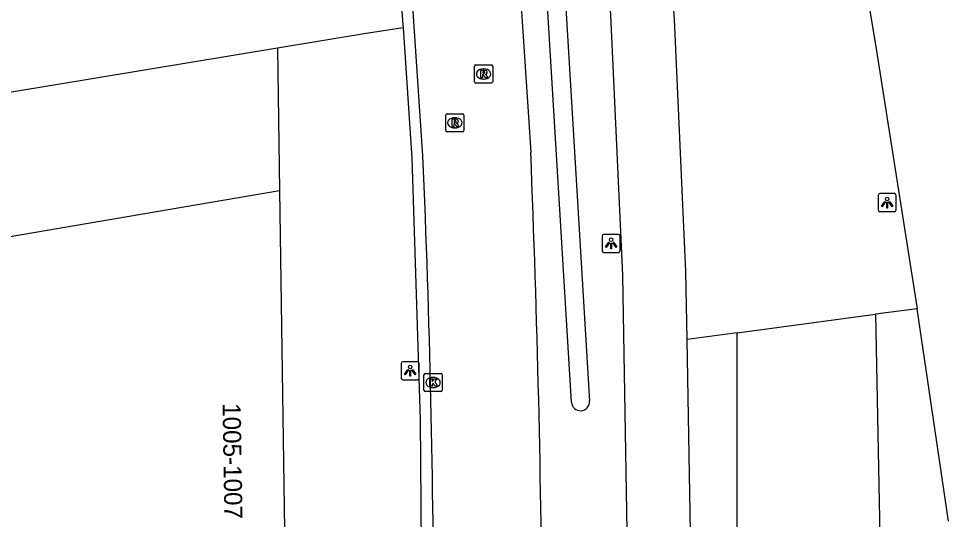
# Model space of a CAD drawing. Extents: x 154324 to 155743, y 382939 to 384183.
# Drawn here: x 155048.2 to 155099.6, y 383314 to 383341.7 of the extents above; entities that cross this region are included whole.
import ezdxf

# ---------------------------------------------------------------- set-up
doc = ezdxf.new("R2010")
doc.units = 0
for name, color, linetype in [('IMGEO_Berm_groen', 7, 'Continuous'), ('IMGEO_Fietspad_gesloten', 7, 'Continuous'), ('IMGEO_Grasland_agrarisch', 7, 'Continuous'), ('IMGEO_Greppel_droge_sloot', 7, 'Continuous'), ('IMGEO_Kolk', 7, 'Continuous'), ('IMGEO_Lichtpunt', 7, 'Continuous'), ('IMGEO_Pand', 7, 'Continuous'), ('IMGEO_Pand_nummerreeks', 7, 'Continuous'), ('IMGEO_Parkeervlak_open', 7, 'Continuous'), ('IMGEO_Rijbaan_lokaal_gesloten', 7, 'Continuous'), ('IMGEO_Rijbaan_lokaal_open', 7, 'Continuous'), ('IMGEO_Rijbaan_regionaal_gesloten', 7, 'Continuous'), ('IMGEO_Rioolput', 7, 'Continuous')]:
    doc.layers.add(name, color=color, linetype=linetype)

msp = doc.modelspace()

# ---------------------------------------------------------------- linework, layer by layer
at = {"layer": 'IMGEO_Berm_groen'}
for points in [[(155097.848, 383325.634), (155095.535, 383325.326)], [(155095.535, 383325.326), (155095.807, 383312.144), (155096.776, 383295.415), (155092.963, 383270.8), (155089.107, 383257.395), (155085.714, 383250.375), (155080.634, 383240.078), (155071.266, 383224.593), (155061.11, 383215.947), (155071.677, 383232.691), (155081.284, 383251.493), (155083.628, 383259.846), (155086.643, 383270.638), (155087.872, 383284.02), (155087.88, 383295.431), (155087.898, 383324.309)], [(155087.898, 383324.309), (155095.535, 383325.326)], [(155087.898, 383324.309), (155085.135, 383323.941)]]:
    msp.add_lwpolyline(points, dxfattribs=at)
at = {"layer": 'IMGEO_Fietspad_gesloten'}
for points in [[(155077.17, 383394.842), (155080.905, 383341.835), (155081.566, 383327.494), (155081.827, 383312.283), (155081.9, 383290.584)], [(155085.135, 383323.941), (155085.067, 383327.696), (155084.447, 383341.596), (155080.698, 383395.149)], [(155085.424, 383290.508), (155085.346, 383312.247), (155085.135, 383323.941)]]:
    msp.add_lwpolyline(points, dxfattribs=at)
at = {"layer": 'IMGEO_Grasland_agrarisch'}
msp.add_lwpolyline([(155062.526, 383340.029), (155003.646, 383330.283)], dxfattribs=at)
at = {"layer": 'IMGEO_Greppel_droge_sloot'}
for points in [[(155078.754, 383320.472), (155076.223, 383362.405)], [(155077.221, 383362.465), (155079.752, 383320.532)]]:
    msp.add_lwpolyline(points, dxfattribs=at)
msp.add_arc((155079.253, 383320.502), 0.5, 183.4452, 3.4358, dxfattribs=at)
at = {"layer": 'IMGEO_Kolk'}
for p, q in [((155070.61, 383321.133), (155070.61, 383321.985)), ((155070.685, 383322.059), (155071.537, 383322.059)), ((155071.098, 383321.839), (155071.123, 383321.839)), ((155071.611, 383321.985), (155071.611, 383321.133)), ((155071.121, 383321.279), (155071.096, 383321.279)), ((155071.537, 383321.059), (155070.685, 383321.059))]:
    msp.add_line(p, q, dxfattribs=at)
for points in [[(155070.61, 383321.133), (155070.61, 383321.985)], [(155070.685, 383322.059), (155071.537, 383322.059)], [(155071.611, 383321.985), (155071.611, 383321.133)], [(155070.931, 383321.759), (155071.054, 383321.759), (155071.054, 383321.608), (155071.184, 383321.759), (155071.348, 383321.759), (155071.202, 383321.608), (155071.355, 383321.359), (155071.203, 383321.359), (155071.118, 383321.523), (155071.054, 383321.456), (155071.054, 383321.359), (155070.931, 383321.359), (155070.931, 383321.759)], [(155071.537, 383321.059), (155070.685, 383321.059)]]:
    msp.add_lwpolyline(points, dxfattribs=at)
for centre, start, end in [((155070.687, 383321.983), 91.552, 178.448), ((155070.687, 383321.983), 91.552, 178.448), ((155071.535, 383321.983), 1.552, 88.448), ((155071.535, 383321.983), 1.552, 88.448), ((155070.687, 383321.135), 181.552, 268.448), ((155070.687, 383321.135), 181.552, 268.448), ((155071.535, 383321.135), 271.552, 358.448), ((155071.535, 383321.135), 271.552, 358.448)]:
    msp.add_arc(centre, 0.0765, start, end, dxfattribs=at)
for centre, major_axis, ratio, start_param, end_param in [((155071.097, 383321.559), (-0.387, 0.002), 0.722429, 4.712389, 7.853982), ((155071.122, 383321.559), (-0.39, 0.002), 0.717154, 1.570796, 4.712389)]:
    msp.add_ellipse(centre, major_axis=major_axis, ratio=ratio, start_param=start_param, end_param=end_param, dxfattribs=at)
at = {"layer": 'IMGEO_Lichtpunt'}
for p, q in [((155095.685, 383331.895), (155095.685, 383331.088)), ((155095.685, 383331.895), (155095.685, 383331.088)), ((155096.587, 383331.99), (155095.779, 383331.99)), ((155096.587, 383331.99), (155095.779, 383331.99)), ((155096.681, 383331.088), (155096.681, 383331.895)), ((155096.681, 383331.088), (155096.681, 383331.895)), ((155095.779, 383330.994), (155096.587, 383330.994)), ((155095.779, 383330.994), (155096.587, 383330.994)), ((155080.446, 383329.646), (155080.446, 383328.839)), ((155080.446, 383329.646), (155080.446, 383328.839)), ((155081.348, 383329.741), (155080.54, 383329.741)), ((155081.348, 383329.741), (155080.54, 383329.741)), ((155081.442, 383328.839), (155081.442, 383329.646)), ((155081.442, 383328.839), (155081.442, 383329.646)), ((155080.54, 383328.745), (155081.348, 383328.745)), ((155080.54, 383328.745), (155081.348, 383328.745)), ((155069.348, 383322.616), (155069.348, 383321.809)), ((155069.348, 383322.616), (155069.348, 383321.809)), ((155070.25, 383322.711), (155069.442, 383322.711)), ((155070.25, 383322.711), (155069.442, 383322.711)), ((155070.344, 383321.809), (155070.344, 383322.616)), ((155070.344, 383321.809), (155070.344, 383322.616)), ((155069.442, 383321.715), (155070.25, 383321.715)), ((155069.442, 383321.715), (155070.25, 383321.715))]:
    msp.add_line(p, q, dxfattribs=at)
for points in [[(155096.059, 383331.559), (155096.098, 383331.531), (155095.91, 383331.269), (155095.872, 383331.296), (155096.059, 383331.559)], [(155096.271, 383331.531), (155096.309, 383331.558), (155096.496, 383331.296), (155096.457, 383331.268), (155096.271, 383331.531)], [(155096.161, 383331.511), (155096.208, 383331.511), (155096.208, 383331.189), (155096.161, 383331.189), (155096.161, 383331.511)], [(155080.82, 383329.31), (155080.859, 383329.282), (155080.671, 383329.02), (155080.633, 383329.047), (155080.82, 383329.31)], [(155080.922, 383329.262), (155080.969, 383329.262), (155080.969, 383328.94), (155080.922, 383328.94), (155080.922, 383329.262)], [(155081.032, 383329.282), (155081.07, 383329.309), (155081.257, 383329.047), (155081.218, 383329.019), (155081.032, 383329.282)], [(155069.722, 383322.28), (155069.761, 383322.252), (155069.573, 383321.99), (155069.535, 383322.017), (155069.722, 383322.28)], [(155069.824, 383322.232), (155069.871, 383322.232), (155069.871, 383321.91), (155069.824, 383321.91), (155069.824, 383322.232)], [(155069.934, 383322.252), (155069.972, 383322.279), (155070.159, 383322.017), (155070.12, 383321.989), (155069.934, 383322.252)]]:
    msp.add_lwpolyline(points, dxfattribs=at)
for centre in [(155096.184, 383331.693), (155080.945, 383329.444), (155069.847, 383322.414)]:
    msp.add_circle(centre, 0.0994, dxfattribs=at)
for centre, start, end in [((155095.779, 383331.895), 90, 180), ((155095.779, 383331.895), 90, 180), ((155096.587, 383331.895), 0, 90), ((155096.587, 383331.895), 0, 90), ((155095.779, 383331.088), 180, 270), ((155095.779, 383331.088), 180, 270), ((155096.587, 383331.088), 270, 0), ((155096.587, 383331.088), 270, 360), ((155080.54, 383329.646), 90, 180), ((155080.54, 383329.646), 90, 180), ((155081.348, 383329.646), 0, 90), ((155081.348, 383329.646), 0, 90), ((155080.54, 383328.839), 180, 270), ((155080.54, 383328.839), 180, 270), ((155081.348, 383328.839), 270, 0), ((155081.348, 383328.839), 270, 360), ((155069.442, 383322.616), 90, 180), ((155069.442, 383322.616), 90, 180), ((155070.25, 383322.616), 0, 90), ((155070.25, 383322.616), 0, 90), ((155069.442, 383321.809), 180, 270), ((155069.442, 383321.809), 180, 270), ((155070.25, 383321.809), 270, 0), ((155070.25, 383321.809), 270, 360)]:
    msp.add_arc(centre, 0.0946, start, end, dxfattribs=at)
at = {"layer": 'IMGEO_Pand'}
for points in [[(155023.637, 383278.886), (155015.928, 383324.201), (155062.639, 383332.154)], [(155062.639, 383332.154), (155063.103, 383299.681), (155049.179, 383297.317), (155050.459, 383289.779), (155050.501, 383289.532), (155051.339, 383284.597), (155051.381, 383284.351), (155051.414, 383284.155), (155063.294, 383286.173)]]:
    msp.add_lwpolyline(points, dxfattribs=at)
at = {"layer": 'IMGEO_Parkeervlak_open'}
for points in [[(155069.458, 383341.15), (155067.422, 383340.839), (155062.526, 383340.029)], [(155062.526, 383340.029), (155062.639, 383332.154)]]:
    msp.add_lwpolyline(points, dxfattribs=at)
at = {"layer": 'IMGEO_Rijbaan_lokaal_gesloten'}
for points in [[(155072.788, 383390.399), (155076.503, 383334.279)], [(155070.546, 383334.082), (155066.805, 383389.917)]]:
    msp.add_lwpolyline(points, dxfattribs=at)
for centre, radius, start, end in [((154286.606, 383301.933), 790.559, 0.364725, 2.34496), ((154441.799, 383306.417), 629.355, 0.059169, 2.519395)]:
    msp.add_arc(centre, radius, start, end, dxfattribs=at)
at = {"layer": 'IMGEO_Rijbaan_lokaal_open'}
for points in [[(155065.709, 383396.485), (155066.213, 383389.857), (155069.432, 383341.538), (155069.458, 383341.15)], [(155069.458, 383341.15), (155069.938, 383333.947), (155070.4, 383319.494), (155070.638, 383289.04)]]:
    msp.add_lwpolyline(points, dxfattribs=at)
at = {"layer": 'IMGEO_Rijbaan_regionaal_gesloten'}
for points in [[(155071.187, 383485.369), (155076.819, 383452.367), (155095.519, 383340.332), (155097.848, 383325.634)], [(155099.567, 383313.904), (155097.848, 383325.634)]]:
    msp.add_lwpolyline(points, dxfattribs=at)
at = {"layer": 'IMGEO_Rioolput'}
for p, q in [((155073.402, 383338.17), (155073.402, 383339.022)), ((155073.477, 383339.096), (155074.329, 383339.096)), ((155073.89, 383338.876), (155073.915, 383338.876)), ((155074.403, 383339.022), (155074.403, 383338.17)), ((155073.913, 383338.316), (155073.888, 383338.316)), ((155074.329, 383338.096), (155073.477, 383338.096)), ((155071.813, 383335.474), (155071.813, 383336.326)), ((155071.888, 383336.4), (155072.74, 383336.4)), ((155072.301, 383336.18), (155072.326, 383336.18)), ((155072.814, 383336.326), (155072.814, 383335.474)), ((155072.74, 383335.4), (155071.888, 383335.4)), ((155072.324, 383335.62), (155072.299, 383335.62))]:
    msp.add_line(p, q, dxfattribs=at)
for points in [[(155073.402, 383338.17), (155073.402, 383339.022)], [(155073.477, 383339.096), (155074.329, 383339.096)], [(155073.991, 383338.794), (155073.739, 383338.796), (155073.739, 383338.396)], [(155073.917, 383338.715), (155073.863, 383338.715), (155073.863, 383338.634)], [(155074.403, 383339.022), (155074.403, 383338.17)], [(155073.739, 383338.396), (155073.863, 383338.396), (155073.863, 383338.558), (155073.874, 383338.558)], [(155073.863, 383338.634), (155073.915, 383338.634)], [(155073.921, 383338.529), (155073.992, 383338.396), (155074.132, 383338.396), (155074.067, 383338.522)], [(155074.329, 383338.096), (155073.477, 383338.096)], [(155071.813, 383335.474), (155071.813, 383336.326)], [(155071.888, 383336.4), (155072.74, 383336.4)], [(155072.814, 383336.326), (155072.814, 383335.474)], [(155072.402, 383336.098), (155072.15, 383336.1), (155072.15, 383335.7)], [(155072.15, 383335.7), (155072.274, 383335.7), (155072.274, 383335.862), (155072.285, 383335.862)], [(155072.328, 383336.019), (155072.274, 383336.019), (155072.274, 383335.938)], [(155072.274, 383335.938), (155072.326, 383335.938)], [(155072.332, 383335.833), (155072.403, 383335.7), (155072.543, 383335.7), (155072.478, 383335.826)], [(155072.74, 383335.4), (155071.888, 383335.4)]]:
    msp.add_lwpolyline(points, dxfattribs=at)
for centre, radius, start, end in [((155073.479, 383339.02), 0.0765, 91.552, 178.448), ((155073.479, 383339.02), 0.0765, 91.552, 178.448), ((155073.923, 383338.619), 0.0964, 77.0061, 93.1865), ((155073.99, 383338.684), 0.109, 350.3612, 89.416), ((155074.327, 383339.02), 0.0765, 1.552, 88.448), ((155074.327, 383339.02), 0.0765, 1.552, 88.448), ((155073.873, 383338.505), 0.0533, 26.0293, 88.6989), ((155073.899, 383338.823), 0.19, 274.7715, 282.9687), ((155073.937, 383338.676), 0.0378, 276.6634, 79.6772), ((155073.988, 383338.684), 0.112, 277.5842, 350.9817), ((155073.972, 383338.469), 0.108, 29.5134, 73.7905), ((155073.479, 383338.172), 0.0765, 181.552, 268.448), ((155073.479, 383338.172), 0.0765, 181.552, 268.448), ((155074.327, 383338.172), 0.0765, 271.552, 358.448), ((155074.327, 383338.172), 0.0765, 271.552, 358.448), ((155071.89, 383336.324), 0.0765, 91.552, 178.448), ((155071.89, 383336.324), 0.0765, 91.552, 178.448), ((155072.738, 383336.324), 0.0765, 1.552, 88.448), ((155072.738, 383336.324), 0.0765, 1.552, 88.448), ((155072.284, 383335.809), 0.0533, 26.0293, 88.6989), ((155072.31, 383336.127), 0.19, 274.7715, 282.9687), ((155072.334, 383335.923), 0.0964, 77.0061, 93.1865), ((155072.348, 383335.98), 0.0378, 276.6634, 79.6772), ((155072.401, 383335.988), 0.109, 350.3612, 89.416), ((155072.399, 383335.988), 0.112, 277.5842, 350.9817), ((155072.383, 383335.773), 0.108, 29.5134, 73.7905), ((155071.89, 383335.476), 0.0765, 181.552, 268.448), ((155071.89, 383335.476), 0.0765, 181.552, 268.448), ((155072.738, 383335.476), 0.0765, 271.552, 358.448), ((155072.738, 383335.476), 0.0765, 271.552, 358.448)]:
    msp.add_arc(centre, radius, start, end, dxfattribs=at)
for centre, major_axis, ratio, start_param, end_param in [((155073.889, 383338.596), (-0.387, 0.002), 0.722429, 4.712389, 7.853982), ((155073.914, 383338.596), (-0.39, 0.002), 0.717154, 1.570796, 4.712389), ((155072.3, 383335.9), (-0.387, 0.002), 0.722429, 4.712389, 7.853982), ((155072.325, 383335.9), (-0.39, 0.002), 0.717154, 1.570796, 4.712389)]:
    msp.add_ellipse(centre, major_axis=major_axis, ratio=ratio, start_param=start_param, end_param=end_param, dxfattribs=at)

# ---------------------------------------------------------------- texts
at = {"layer": 'IMGEO_Pand_nummerreeks'}
msp.add_text('1005-1007', height=1, rotation=270.9378, dxfattribs=at).set_placement((155059.486, 383320.413))

doc.saveas('drawing.dxf')
